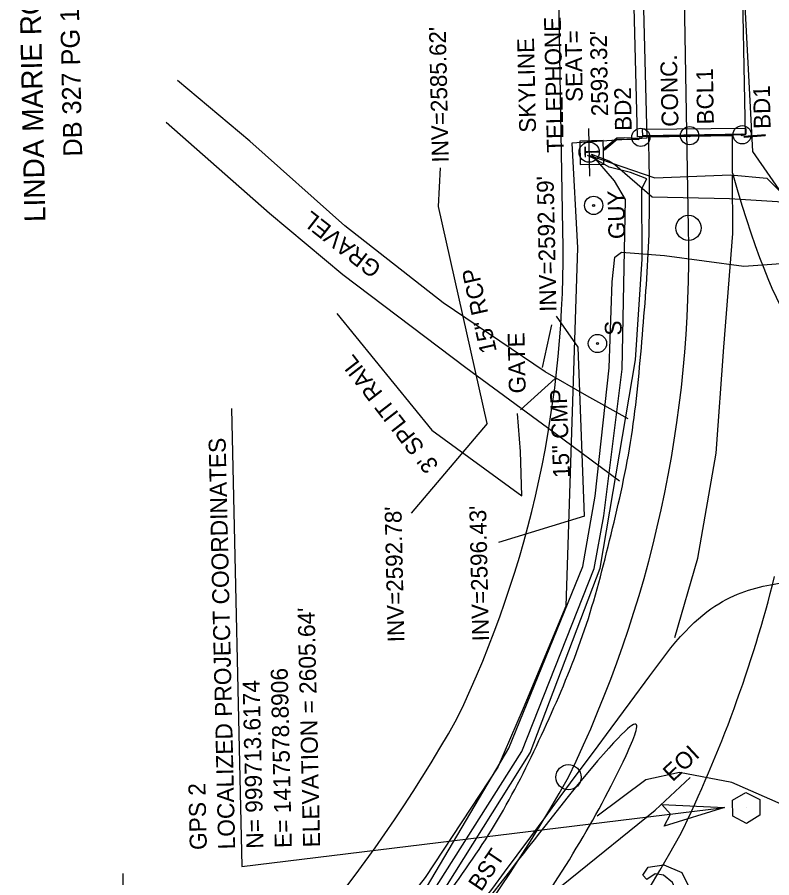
# Model space of a CAD drawing. Extents: x 1417249 to 1417944, y 999313 to 1000321.
# Drawn here: x 1417405 to 1417585, y 999696.9 to 999902.2 of the extents above; entities that cross this region are included whole.
import ezdxf

# ---------------------------------------------------------------- set-up
doc = ezdxf.new("R2010")
doc.units = 0
for name, color, linetype in [('CTL GPS Vertical CELL', 7, 'Continuous'), ('CTL Supplemental Horizontal and Vertical Text', 7, 'Continuous'), ('Default', 7, 'Continuous'), ('Exist Horizontal Alignment', 7, 'Continuous'), ('Exist Horizontal Alignment Point', 7, 'Continuous'), ('Exist Other Culture Anchor (Guy Wire) CELL', 7, 'Continuous'), ('Exist Other Culture Anchor (Guy Wire) Text', 7, 'Continuous'), ('Exist Other Culture Area Outline', 7, 'Continuous'), ('Exist Other Culture Fence Line', 7, 'Continuous'), ('Exist Other Culture Fence Line Text', 7, 'Continuous'), ('Exist Other Culture Gate', 7, 'Continuous'), ('Exist Other Culture Gate Text', 7, 'Continuous'), ('Exist Other Culture Located Object CELL', 7, 'Continuous'), ('Exist Other Culture Located Object Text', 7, 'Continuous'), ('Exist Other Culture Sign CELL', 7, 'Continuous'), ('Exist Other Culture Sign Text', 7, 'Continuous'), ('Exist Property Deed Book Text', 7, 'Continuous'), ('Exist Property Owner Text', 7, 'Continuous'), ('Exist Right of Way Line', 7, 'Continuous'), ('Exist Roads EOP', 7, 'Continuous'), ('Exist Roads EOP Other', 7, 'Continuous'), ('Exist Roads EOP Other Text', 7, 'Continuous'), ('Exist Roads EOP Text', 7, 'Continuous'), ('Exist Roads EOT', 7, 'Continuous'), ('Exist Roads Soil', 7, 'Continuous'), ('Exist Roads Soil Text', 7, 'Continuous'), ('Exist Structure Major Bridge Seat Top Elevation', 7, 'Continuous'), ('Exist Structure Major Bridge WW', 7, 'Continuous'), ('Exist Structure Major Deck Tunnel Box Culvert', 7, 'Continuous'), ('Exist Structure Minor Pipes CMP 15 Inch', 7, 'Continuous'), ('Exist Structure Minor Pipes CMP 15 Inch Invert', 7, 'Continuous'), ('Exist Structure Minor Pipes CMP 15 Inch Text', 7, 'Continuous'), ('Exist Structure Minor Pipes RCP 15 Inch', 7, 'Continuous'), ('Exist Structure Minor Pipes RCP 15 Inch Invert', 7, 'Continuous'), ('Exist Structure Minor Pipes RCP 15 Inch Text', 7, 'Continuous'), ('Exist Utilities Other Unknown UG SUE', 7, 'Continuous'), ('Exist Utilities Other Unknown UG SUE Text', 7, 'Continuous'), ('Exist Utilities Telephone Pedestal CELL', 7, 'Continuous'), ('Exist Utilities Telephone Pole CELL', 7, 'Continuous'), ('Exist Utilities Telephone Pole Text', 7, 'Continuous'), ('Exist Utilities Telephone UG Cable SUE', 7, 'Continuous'), ('Exist Utilities Telephone UG FO SUE', 7, 'Continuous'), ('Exist Vegetation Woods Line', 7, 'Continuous'), ('Old_Level_11', 7, 'Continuous')]:
    doc.layers.add(name, color=color, linetype=linetype)

# ---------------------------------------------------------------- blocks, each defined once
blk = doc.blocks.new('EXIST OTHER CULTURE LOCATED OBJECT')
at = {"layer": 'Exist Other Culture Located Object CELL'}
for radius in [0.0436, 0.0048]:
    blk.add_circle((0, 0), radius, dxfattribs=at)

msp = doc.modelspace()

# ---------------------------------------------------------------- linework, layer by layer
at = {"layer": 'CTL GPS Vertical CELL'}
msp.add_line((1417578.89, 999713.62), (1417578.89, 999713.62), dxfattribs=at)
msp.add_lwpolyline([(1417575.62, 999715.42), (1417578.83, 999717.3), (1417582.12, 999715.58), (1417582.15, 999711.86), (1417578.94, 999709.9), (1417575.7, 999711.65)], close=True, dxfattribs=at)
at = {"layer": 'Default'}
for p, q in [((1417456.13, 999808.88), (1417458.57, 999699.63)), ((1417458.57, 999699.63), (1417573.7, 999713.67))]:
    msp.add_line(p, q, dxfattribs=at)
at = {"layer": 'Exist Horizontal Alignment'}
msp.add_line((1417565.14, 999851.97), (1417563.2, 999963.97), dxfattribs=at)
for centre, radius, start, end in [((1417280.02, 999845.64), 285.19, 334.0675, 1.2727), ((1417207.54, 999905.42), 377.16, 309.1897, 330.7144)]:
    msp.add_arc(centre, radius, start, end, dxfattribs=at)
at = {"layer": 'Exist Horizontal Alignment Point'}
for centre in [(1417565.14, 999851.97), (1417536.5, 999720.92)]:
    msp.add_circle(centre, 3, dxfattribs=at)
at = {"layer": 'Exist Other Culture Anchor (Guy Wire) CELL'}
for radius in [2.18, 0.24]:
    msp.add_circle((1417542.51, 999857.34), radius, dxfattribs=at)
at = {"layer": 'Exist Other Culture Area Outline'}
msp.add_lwpolyline([(1417555.17, 999696.53), (1417554.24, 999697.57), (1417555.52, 999699.42), (1417559.28, 999700.01), (1417563.51, 999698.15), (1417565.3, 999694.57), (1417563.75, 999691.06), (1417562.83, 999690.94), (1417562.29, 999693.6), (1417561.35, 999695.82), (1417559.17, 999697.56), (1417557.17, 999697.83), (1417555.17, 999696.53)], dxfattribs=at)
at = {"layer": 'Exist Other Culture Fence Line'}
msp.add_line((1417530.28, 999818.66), (1417532.54, 999828.83), dxfattribs=at)
msp.add_lwpolyline([(1417481.27, 999831.51), (1417503.89, 999803.69), (1417525.34, 999788.08), (1417525.08, 999798.61), (1417524.36, 999807.68)], dxfattribs=at)
at = {"layer": 'Exist Other Culture Gate'}
msp.add_line((1417525.05, 999808.58), (1417533.29, 999816.05), dxfattribs=at)
at = {"layer": 'Exist Other Culture Sign CELL'}
for radius in [2.18, 0.24]:
    msp.add_circle((1417543.42, 999824.39), radius, dxfattribs=at)
at = {"layer": 'Exist Right of Way Line'}
msp.add_line((1417535.15, 999851.38), (1417533.2, 999963.46), dxfattribs=at)
for centre, radius, start, end in [((1417280.02, 999845.64), 255.19, 334.2633, 1.2886), ((1417280.02, 999845.64), 315.19, 333.907, 345.8853), ((1417207.54, 999905.42), 347.16, 309.1897, 330.5684), ((1417207.54, 999905.42), 407.16, 309.1897, 330.8372)]:
    msp.add_arc(centre, radius, start, end, dxfattribs=at)
at = {"layer": 'Exist Roads EOP'}
for points in [[(1417555.64, 999873.66), (1417565.36, 999873.82), (1417575.61, 999874.01)], [(1417575.63, 999865.05), (1417575.61, 999874.01)], [(1417657.17, 999749.26), (1417644.36, 999753.18), (1417636.32, 999753.63), (1417633.36, 999752.85), (1417628.34, 999747.97), (1417627.51, 999744.62), (1417626.64, 999741.01), (1417621.38, 999732.08), (1417618.13, 999723.71), (1417618.76, 999718.4), (1417623.59, 999710.2), (1417621.5, 999701.87), (1417610.96, 999702.3), (1417592.37, 999712.28), (1417575.45, 999719.66), (1417563.02, 999722.02), (1417554.96, 999720.26), (1417543.34, 999711.65)]]:
    msp.add_lwpolyline(points, dxfattribs=at)
for points in [[(1417439.85, 999620.47), (1417440.86, 999621.35), (1417448.28, 999627.85), (1417460.93, 999639.72), (1417479.6, 999658.21), (1417494.78, 999676.05), (1417510.16, 999695.92), (1417521.93, 999713.7), (1417532.12, 999735.03), (1417540.79, 999755.62), (1417546.81, 999778.87), (1417552.06, 999801.98), (1417554.17, 999826.56), (1417556.13, 999850.29), (1417555.8, 999866.43), (1417555.64, 999873.66)], [(1417575.63, 999865.05), (1417581.75, 999843.36), (1417591.73, 999822.61), (1417605.87, 999805.34), (1417623.78, 999791.13), (1417575.63, 999865.05), (1417623.78, 999791.13)], [(1417560.92, 999751.8), (1417567.38, 999759.55), (1417576.89, 999765.72), (1417590.73, 999768.05), (1417604.66, 999766.99), (1417631.14, 999759.99), (1417560.92, 999751.8), (1417631.14, 999759.99)], [(1417452.41, 999605.46), (1417455.22, 999607.6), (1417478.07, 999628.46), (1417491.77, 999642.25), (1417509.79, 999663.12), (1417524.31, 999681.77), (1417538.87, 999704.21), (1417550.4, 999725.14), (1417560.92, 999751.8), (1417452.41, 999605.46), (1417560.92, 999751.8)]]:
    msp.add_open_spline(points, degree=3, dxfattribs=at)
at = {"layer": 'Exist Roads EOP Other'}
for p, q in [((1417578.81, 999875.71), (1417554.11, 999875.45)), ((1417554.11, 999875.45), (1417554.13, 999873.91)), ((1417578.82, 999874.34), (1417554.13, 999873.91)), ((1417578.81, 999875.71), (1417578.82, 999874.34))]:
    msp.add_line(p, q, dxfattribs=at)
at = {"layer": 'Exist Roads EOT'}
msp.add_lwpolyline([(1417561.87, 999754.25), (1417567.35, 999773.19), (1417571.77, 999798.25), (1417573.56, 999823.52), (1417575.75, 999850.63), (1417575.64, 999864.5)], dxfattribs=at)
at = {"layer": 'Exist Roads Soil'}
for points in [[(1417550.72, 999806.4), (1417540.85, 999811.88), (1417530.94, 999817.66), (1417506.64, 999834.1), (1417483.14, 999852.48), (1417460.51, 999872.64), (1417443.21, 999887.15)], [(1417440.48, 999877.19), (1417465.17, 999855.47), (1417482.69, 999840.89), (1417512, 999818.64), (1417532.98, 999803.22), (1417548.7, 999791.6)]]:
    msp.add_lwpolyline(points, dxfattribs=at)
at = {"layer": 'Exist Structure Major Bridge WW'}
for points in [[(1417578.32, 999873.79), (1417578.41, 999873.59), (1417581.5, 999873.82), (1417583.47, 999874), (1417583.48, 999874.2), (1417581.51, 999874.02), (1417578.32, 999873.79)], [(1417553.32, 999873.29), (1417549.78, 999873.43), (1417548.01, 999873.37), (1417544.88, 999870.73), (1417545.09, 999870.57), (1417548.1, 999873.1), (1417549.77, 999873.16), (1417553.32, 999873.02), (1417553.32, 999873.29), (1417553.32, 999873.02)]]:
    msp.add_lwpolyline(points, dxfattribs=at)
at = {"layer": 'Exist Structure Major Deck Tunnel Box Culvert'}
msp.add_lwpolyline([(1417550.63, 999963.4), (1417576.91, 999963.98), (1417578.68, 999874.14), (1417552.94, 999873.67)], close=True, dxfattribs=at)
at = {"layer": 'Exist Structure Minor Pipes CMP 15 Inch'}
msp.add_line((1417540.34, 999783.17), (1417538.79, 999823.55), dxfattribs=at)
at = {"layer": 'Exist Structure Minor Pipes CMP 15 Inch Invert'}
for points in [[(1417538.79, 999823.55), (1417533.61, 999830.91)], [(1417540.34, 999783.17), (1417519.82, 999776.95)]]:
    msp.add_lwpolyline(points, dxfattribs=at)
at = {"layer": 'Exist Structure Minor Pipes RCP 15 Inch'}
msp.add_line((1417517.11, 999805.32), (1417505.49, 999857.06), dxfattribs=at)
at = {"layer": 'Exist Structure Minor Pipes RCP 15 Inch Invert'}
for points in [[(1417505.49, 999857.06), (1417505.94, 999866.3)], [(1417517.11, 999805.32), (1417499, 999783.9)]]:
    msp.add_lwpolyline(points, dxfattribs=at)
at = {"layer": 'Exist Utilities Other Unknown UG SUE'}
msp.add_lwpolyline([(1417476.44, 999649.53), (1417516.66, 999680.26), (1417557.21, 999713.08), (1417565.5, 999720.83)], dxfattribs=at)
at = {"layer": 'Exist Utilities Telephone Pedestal CELL'}
msp.add_line((1417542.02, 999869.85), (1417542.02, 999869.85), dxfattribs=at)
msp.add_lwpolyline([(1417544.91, 999867.2), (1417544.78, 999872.79), (1417539.18, 999872.65), (1417539.32, 999867.06), (1417544.91, 999867.2)], dxfattribs=at)
at = {"layer": 'Exist Utilities Telephone Pole CELL'}
for p, q in [((1417541.59, 999864.35), (1417541.32, 999875.69)), ((1417541.45, 999870.03), (1417541.45, 999870.03))]:
    msp.add_line(p, q, dxfattribs=at)
msp.add_circle((1417541.45, 999870.03), 2.41, dxfattribs=at)
at = {"layer": 'Exist Utilities Telephone UG Cable SUE'}
for points in [[(1417469.68, 999655.41), (1417501.04, 999688.68), (1417525.41, 999727.08), (1417542.66, 999770.68), (1417544.91, 999783.26), (1417549.3, 999818.25), (1417550.07, 999858.75), (1417547.47, 999863.17), (1417541.97, 999869.57)], [(1417541.97, 999869.57), (1417546.14, 999867.98), (1417547.57, 999867.07), (1417556.49, 999859.36), (1417574.93, 999859.01), (1417586.41, 999858.26), (1417589.59, 999857.53), (1417592.95, 999853.3), (1417594.32, 999851.29), (1417593.73, 999848.07), (1417591.79, 999844.34), (1417603.62, 999810.67), (1417620.71, 999796.33), (1417633.83, 999788.28), (1417667.2, 999769.98)]]:
    msp.add_lwpolyline(points, dxfattribs=at)
at = {"layer": 'Exist Utilities Telephone UG FO SUE'}
for points in [[(1417471.43, 999653.55), (1417502.55, 999687.24), (1417527.4, 999726.75), (1417544.07, 999770.83), (1417552.47, 999820.51), (1417554.12, 999844.53), (1417553.97, 999861.39), (1417555.21, 999863.67), (1417551.27, 999865.18), (1417546.23, 999866.44), (1417543.01, 999868.31), (1417541.06, 999869.26)], [(1417541.38, 999869.29), (1417557.07, 999863.91), (1417575.14, 999864.61), (1417583.79, 999863.82), (1417595.69, 999852.02)], [(1417467.59, 999656.83), (1417499.73, 999689.79), (1417522.28, 999727.87), (1417539.9, 999771.2), (1417542.88, 999787.94), (1417546.19, 999818.6), (1417546.93, 999839.08), (1417547.54, 999844.95), (1417549.16, 999846.16), (1417559.4, 999845.4), (1417578.31, 999842.88), (1417592.74, 999843.86), (1417594.44, 999847.99), (1417596.21, 999851.03)]]:
    msp.add_lwpolyline(points, dxfattribs=at)
at = {"layer": 'Exist Vegetation Woods Line'}
for points in [[(1417580.46, 999870.2), (1417578.16, 999914.11), (1417575.47, 999968.19), (1417569.51, 1000013.81), (1417554.85, 1000066.95), (1417534.46, 1000111.85), (1417506.86, 1000156.7), (1417485.45, 1000196.25), (1417470.81, 1000240.08)], [(1417451.06, 1000235.71), (1417460.15, 1000197.18), (1417483.87, 1000152.84), (1417505.64, 1000117.31), (1417527.8, 1000077.64), (1417539.61, 1000042.27), (1417549.29, 999996.88), (1417553.54, 999938.26), (1417555.22, 999873.36)], [(1417555.22, 999873.36), (1417537.31, 999872.21), (1417538.64, 999847.18), (1417535.89, 999761.69), (1417525.68, 999737.3), (1417519.66, 999723.3), (1417502.28, 999696.97), (1417471.79, 999658.06), (1417430.83, 999631.14), (1417430.26, 999697.93)], [(1417678.64, 999762.53), (1417658.28, 999779.42), (1417635.66, 999794.75), (1417624, 999800.57), (1417608.51, 999825.62), (1417599.15, 999843.27), (1417580.46, 999870.2)]]:
    msp.add_lwpolyline(points, dxfattribs=at)
at = {"layer": 'Old_Level_11'}
msp.add_lwpolyline([(1417558.76, 999714.41), (1417573.7, 999713.67), (1417559.3, 999709.28), (1417560.85, 999712.11)], close=True, dxfattribs=at)

# ---------------------------------------------------------------- block references
at = {"layer": 'Exist Other Culture Located Object CELL', "xscale": 50.00000000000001, "yscale": 50.00000000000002, "rotation": -11.833767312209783}
for p in [(1417553.76, 999873.57), (1417565.4, 999873.97), (1417577.95, 999874.19)]:
    msp.add_blockref('EXIST OTHER CULTURE LOCATED OBJECT', p, dxfattribs=at)

# ---------------------------------------------------------------- texts
at = {"layer": 'CTL Supplemental Horizontal and Vertical Text'}
for s, p in [('LOCALIZED PROJECT COORDINATES', (1417456.99, 999703.75)), ("ELEVATION = 2605.64'", (1417477.26, 999704.23)), ('E= 1417578.8906', (1417470.5, 999704.07)), ('N= 999713.6174', (1417463.74, 999703.91)), ('GPS 2', (1417450.23, 999703.6))]:
    msp.add_text(s, height=4.055, rotation=91.3473, dxfattribs=at).set_placement(p)
at = {"layer": 'Exist Other Culture Anchor (Guy Wire) Text'}
msp.add_text('GUY', height=4, rotation=91.2799, dxfattribs=at).set_placement((1417550.06, 999849.35))
at = {"layer": 'Exist Other Culture Fence Line Text'}
msp.add_text("3' SPLIT RAIL", height=4, rotation=127.7741, dxfattribs=at).set_placement((1417505.71, 999795.38))
at = {"layer": 'Exist Other Culture Gate Text'}
msp.add_text('GATE', height=4, rotation=91.2799, dxfattribs=at).set_placement((1417526.31, 999812.53))
at = {"layer": 'Exist Other Culture Located Object Text'}
for s, p in [('BCL1', (1417571.2, 999876.69)), ('BD2', (1417551.59, 999875.16)), ('BD1', (1417584.73, 999875.61))]:
    msp.add_text(s, height=4, rotation=91.0252, dxfattribs=at).set_placement(p)
at = {"layer": 'Exist Other Culture Sign Text'}
msp.add_text('S', height=4, rotation=91.2799, dxfattribs=at).set_placement((1417549.23, 999826.33))
at = {"layer": 'Exist Property Deed Book Text'}
msp.add_text('DB 327 PG 1001', height=4.5, rotation=91.2799, dxfattribs=at).set_placement((1417420.5, 999869.05))
at = {"layer": 'Exist Property Owner Text'}
msp.add_text('LINDA MARIE ROBERTS', height=5, rotation=91.2799, dxfattribs=at).set_placement((1417411.73, 999853.42))
at = {"layer": 'Exist Roads EOP Other Text'}
msp.add_text('CONC.', height=4, rotation=91.2799, dxfattribs=at).set_placement((1417562.76, 999876.15))
at = {"layer": 'Exist Roads EOP Text'}
msp.add_text('BST', height=4, rotation=56.2461, dxfattribs=at).set_placement((1417515.66, 999693.44))
at = {"layer": 'Exist Roads Soil Text'}
msp.add_text('GRAVEL', height=4, rotation=141.9754, dxfattribs=at).set_placement((1417492.18, 999842.87))
at = {"layer": 'Exist Structure Major Bridge Seat Top Elevation'}
for s, p in [('SEAT=', (1417539.92, 999882.05)), ("2593.32'", (1417545.98, 999878.66))]:
    msp.add_text(s, height=4, rotation=90.9888, dxfattribs=at).set_placement(p)
at = {"layer": 'Exist Structure Minor Pipes CMP 15 Inch Invert'}
for s, p in [("INV=2592.59'", (1417533.66, 999831.99)), ("INV=2596.43'", (1417517.56, 999753.39))]:
    msp.add_text(s, height=4, rotation=91.2799, dxfattribs=at).set_placement(p)
at = {"layer": 'Exist Structure Minor Pipes CMP 15 Inch Text'}
msp.add_text('15" CMP', height=4, rotation=92.1944, dxfattribs=at).set_placement((1417536.86, 999792.39))
at = {"layer": 'Exist Structure Minor Pipes RCP 15 Inch Invert'}
for s, p in [("INV=2585.62'", (1417507.94, 999867.61)), ("INV=2592.78'", (1417497.36, 999753.17))]:
    msp.add_text(s, height=4, rotation=91.2799, dxfattribs=at).set_placement(p)
at = {"layer": 'Exist Structure Minor Pipes RCP 15 Inch Text'}
msp.add_text('15" RCP', height=4, rotation=102.665, dxfattribs=at).set_placement((1417519.43, 999822.54))
at = {"layer": 'Exist Utilities Other Unknown UG SUE Text'}
msp.add_text('EOI', height=4, rotation=43.0603, dxfattribs=at).set_placement((1417561.33, 999719.67))
at = {"layer": 'Exist Utilities Telephone Pedestal CELL'}
msp.add_text('T', height=3.42, rotation=91.3853, dxfattribs=at).set_placement((1417543.76, 999868.76))
at = {"layer": 'Exist Utilities Telephone Pole Text'}
for s, p in [('TELEPHONE', (1417535.38, 999869.97)), ('SKYLINE', (1417528.77, 999874.74))]:
    msp.add_text(s, height=4, rotation=91.2799, dxfattribs=at).set_placement(p)

doc.saveas('drawing.dxf')
